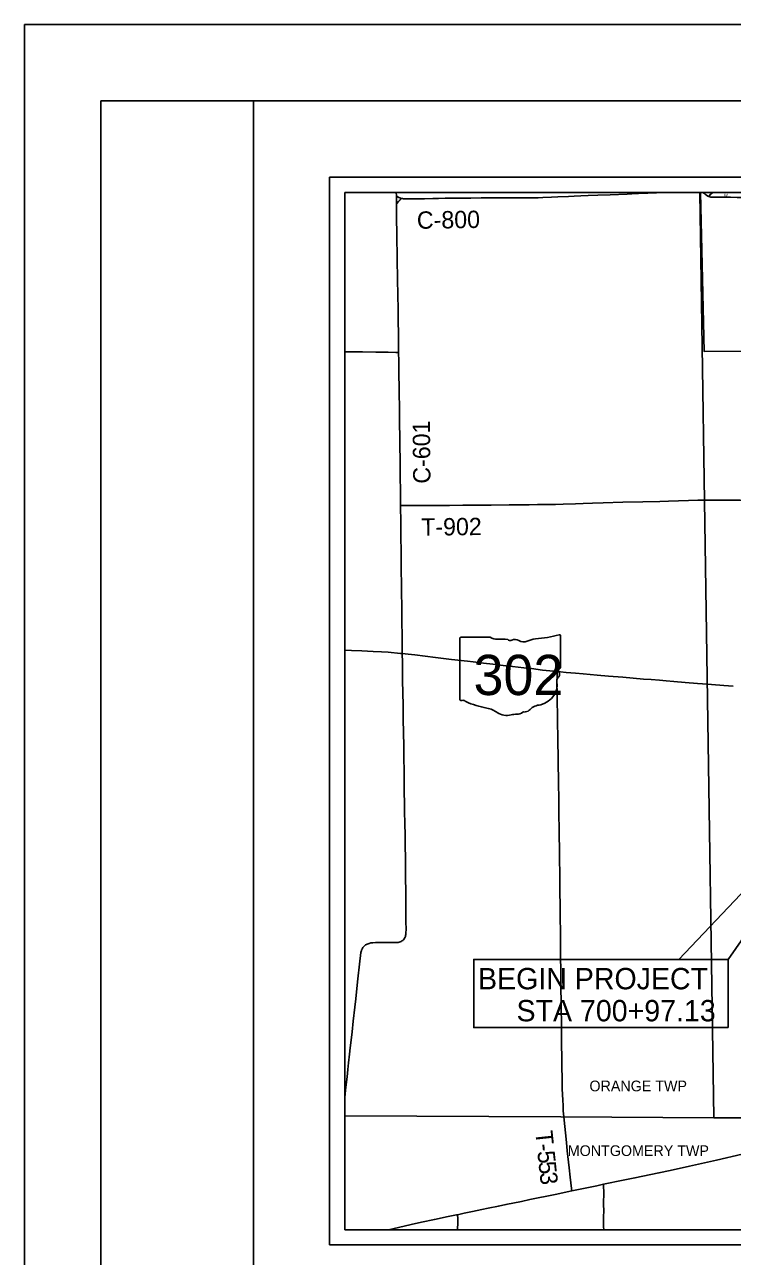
# Model space of a CAD drawing. Extents: x 0 to 72, y -85 to 22.
# Drawn here: x 0 to 4.64, y 13.93 to 22 of the extents above; entities that cross this region are included whole.
import ezdxf

# ---------------------------------------------------------------- set-up
doc = ezdxf.new("R2010")
doc.units = 0
for name, color, linetype in [('Default', 7, 'Continuous'), ('GM_X_Adjacent_County', 7, 'Continuous'), ('GM_X_County', 7, 'Continuous'), ('GM_X_County_Road', 7, 'Continuous'), ('GM_X_County_Road_Text', 7, 'Continuous'), ('GM_X_Interstate_Location', 7, 'Continuous'), ('GM_X_Minor_Lake', 7, 'Continuous'), ('GM_X_Minor_River_Text', 7, 'Continuous'), ('GM_X_Section', 7, 'Continuous'), ('GM_X_Section_Text', 7, 'Continuous'), ('GM_X_State_Location', 7, 'Continuous'), ('GM_X_Township', 7, 'Continuous'), ('GM_X_Township_Road', 7, 'Continuous'), ('GM_X_Township_Road_Text', 7, 'Continuous'), ('GM_X_Township_Subdivision', 7, 'Continuous'), ('GM_X_Township_Subdivision_Text', 7, 'Continuous'), ('GM_X_Township_Text', 7, 'Continuous'), ('GM_X_US_Location', 7, 'Continuous')]:
    doc.layers.add(name, color=color, linetype=linetype)

msp = doc.modelspace()

# ---------------------------------------------------------------- linework, layer by layer
at = {"layer": 'Default'}
for p, q in [((8.9, 20.9), (2.1, 20.9)), ((2.1, 20.9), (2.1, 14.1)), ((8.9, 20.9), (2.1, 20.9)), ((2.1, 20.9), (2.1, 14.1)), ((2.1, 14.1), (8.9, 14.1)), ((2.1, 14.1), (8.9, 14.1))]:
    msp.add_line(p, q, dxfattribs=at)
at = {"layer": 'GM_X_Adjacent_County'}
for points in [[(4.6126, 15.8721), (4.2903, 15.8721), (5.5075, 17.154)], [(4.6126, 15.4251), (4.6126, 15.8721), (2.9445, 15.8721), (2.9445, 15.4251)]]:
    msp.add_lwpolyline(points, close=True, dxfattribs=at)
at = {"layer": 'GM_X_County'}
for points in [[(0.5, 21.5), (1.5, 21.5), (1.5, 0.5), (0.5, 0.5)], [(1.5, 21.5), (33.5, 21.5), (33.5, 0.5), (1.5, 0.5)]]:
    msp.add_lwpolyline(points, close=True, dxfattribs=at)
at = {"layer": 'GM_X_County_Road_Text'}
for points in [[(2.1, 19.8551), (2.1598, 19.8546), (2.2158, 19.8547), (2.3028, 19.8538), (2.3836, 19.8517), (2.4333, 19.851), (2.4524, 19.8508)], [(2.4647, 18.8472), (2.4866, 18.8472), (2.555, 18.8471), (2.6048, 18.8475), (2.7167, 18.848), (2.7851, 18.8485), (2.8722, 18.8496), (2.9593, 18.8499), (3.0589, 18.8507), (3.1771, 18.8513), (3.2641, 18.8518), (3.3077, 18.8521), (3.3635, 18.8533), (3.4319, 18.8543), (3.4817, 18.8545), (3.5314, 18.8556), (3.6122, 18.8587), (3.662, 18.8606), (3.7241, 18.8627), (3.7924, 18.8648), (3.923, 18.8687), (4.0536, 18.8719), (4.1655, 18.8747), (4.2214, 18.8762), (4.3519, 18.8801), (4.4141, 18.8819), (4.459, 18.8836)], [(4.459, 18.8836), (4.5056, 18.8836), (4.5801, 18.8824), (4.6484, 18.8819), (4.6918, 18.8815), (4.7414, 18.8808), (4.7787, 18.8804), (4.8595, 18.8799), (4.9092, 18.8798), (4.9403, 18.8794), (5.0333, 18.878), (5.0954, 18.8773), (5.2072, 18.8763), (5.2756, 18.8759), (5.3502, 18.8751), (5.4124, 18.8744), (5.4559, 18.8746), (5.4647, 18.8744)], [(3.535, 14.8391), (3.5317, 14.88), (3.5301, 14.9139), (3.5284, 14.9484), (3.5251, 15.023), (3.5245, 15.1038), (3.523, 15.1536), (3.522, 15.1847), (3.5222, 15.2406), (3.5212, 15.3027), (3.5203, 15.4146), (3.5178, 15.5887), (3.5162, 15.6882), (3.5152, 15.7939), (3.5146, 15.8933), (3.5134, 15.999), (3.5112, 16.198), (3.5099, 16.3411), (3.509, 16.4219), (3.5084, 16.4592), (3.5076, 16.5027), (3.5072, 16.54), (3.5066, 16.5836), (3.5049, 16.6955), (3.5041, 16.7452), (3.5033, 16.8011), (3.5019, 16.8445), (3.5017, 16.8757), (3.5017, 16.9254), (3.4998, 17.0248), (3.4954, 17.3234), (3.494, 17.4291), (3.4911, 17.6095), (3.4906, 17.6903), (3.4909, 17.7339), (3.4914, 17.7464), (3.4918, 17.7591)], [(3.5883, 14.3539), (3.5865, 14.3702), (3.578, 14.4439), (3.5707, 14.5054), (3.5581, 14.6161), (3.5527, 14.6716), (3.535, 14.8391)], [(3.7968, 14.1), (3.7967, 14.1199), (3.7965, 14.1822), (3.7968, 14.2258), (3.7966, 14.2632), (3.7969, 14.3503), (3.796, 14.3814), (3.7956, 14.3975)], [(2.8393, 14.1), (2.8399, 14.1489), (2.8396, 14.1736), (2.839, 14.1983)]]:
    msp.add_lwpolyline(points, dxfattribs=at)
at = {"layer": 'GM_X_Interstate_Location'}
msp.add_lwpolyline([(4.6467, 17.6627), (4.5847, 17.6673), (4.5042, 17.673), (4.4767, 17.6752), (4.4113, 17.6804), (4.3309, 17.6876), (4.2566, 17.694), (4.2071, 17.6983), (4.1637, 17.7021), (4.1079, 17.7063), (4.0584, 17.7101), (3.9903, 17.7156), (3.9222, 17.7215), (3.8293, 17.7294), (3.755, 17.736), (3.6621, 17.744), (3.6126, 17.7481), (3.5507, 17.7534), (3.5136, 17.7568), (3.4918, 17.7591), (3.3963, 17.769), (3.3225, 17.7781), (3.2731, 17.7836), (3.2361, 17.7875), (3.1991, 17.7916), (3.1559, 17.7963), (3.0695, 17.8065), (3.0078, 17.8139), (2.94, 17.8224), (2.903, 17.8267), (2.7981, 17.8387), (2.6934, 17.8518), (2.5576, 17.8676), (2.5144, 17.8728), (2.4754, 17.8768), (2.4649, 17.8779), (2.3844, 17.8851), (2.341, 17.8885), (2.2851, 17.8913), (2.2106, 17.8951), (2.1423, 17.8978), (2.1, 17.8997)], dxfattribs=at)
at = {"layer": 'GM_X_Minor_Lake'}
for points in [[(4.428, 20.9), (4.5196, 14.8337), (3.516, 14.8392), (2.1, 14.8468)], [(8.9, 14.8286), (4.755, 14.8337), (4.5196, 14.8337), (4.428, 20.9)], [(2.1, 14.8468), (3.516, 14.8392), (4.5196, 14.8337), (4.755, 14.8337), (4.7514, 14.1)]]:
    msp.add_lwpolyline(points, dxfattribs=at)
at = {"layer": 'GM_X_Minor_River_Text'}
msp.add_line((2.4375, 20.8768), (2.4371, 20.9), dxfattribs=at)
for points in [[(2.4382, 20.8261), (2.438, 20.8502), (2.4375, 20.8768)], [(2.4375, 20.8768), (2.4482, 20.8698), (2.4534, 20.8664), (2.4592, 20.8636), (2.4653, 20.8615), (2.471, 20.8602)], [(2.4382, 20.8261), (2.4511, 20.8406), (2.4549, 20.8449), (2.4569, 20.8468), (2.4591, 20.8489), (2.4618, 20.8516), (2.4652, 20.8546), (2.471, 20.8602)], [(2.471, 20.8602), (2.4715, 20.8601), (2.4778, 20.8593), (2.484, 20.8589), (2.5277, 20.8583), (2.5962, 20.8583), (2.621, 20.8588), (2.6768, 20.8598), (2.714, 20.8606), (2.7574, 20.8614), (2.8195, 20.8619), (2.8754, 20.8624), (2.9252, 20.8629), (2.9936, 20.8635), (3.0371, 20.8637), (3.1303, 20.8646), (3.1801, 20.8649), (3.2671, 20.8651), (3.3293, 20.8642), (3.3667, 20.8644), (3.3977, 20.8659), (3.4536, 20.8689), (3.4971, 20.871), (3.5654, 20.874), (3.6027, 20.8759), (3.6461, 20.8774), (3.6959, 20.879), (3.758, 20.8813), (3.8387, 20.8846), (3.9505, 20.8894), (3.9815, 20.8907), (4.025, 20.892), (4.0871, 20.8946), (4.1431, 20.897), (4.2055, 20.9)], [(2.4524, 19.8508), (2.4512, 19.9373), (2.4507, 19.9808), (2.4498, 20.0491), (2.4482, 20.1424), (2.4466, 20.2169), (2.4461, 20.2418), (2.4448, 20.3162), (2.4441, 20.3721), (2.4437, 20.4218), (2.4431, 20.4715), (2.4422, 20.5212), (2.4416, 20.5647), (2.441, 20.5958), (2.4402, 20.6455), (2.4394, 20.7136), (2.4391, 20.7508), (2.4387, 20.7819), (2.4382, 20.8254), (2.4382, 20.8261)], [(2.4588, 19.371), (2.4586, 19.3842), (2.458, 19.4215), (2.4574, 19.4712), (2.4562, 19.6017), (2.4545, 19.726), (2.4534, 19.7943), (2.4524, 19.8508)], [(2.4647, 18.8472), (2.4647, 18.8498), (2.4639, 18.9244), (2.4623, 19.0549), (2.4613, 19.1606), (2.4607, 19.2227), (2.4599, 19.2724), (2.4594, 19.3159), (2.4589, 19.3656), (2.4588, 19.371)], [(2.4754, 17.8768), (2.475, 17.8927), (2.4745, 17.9859), (2.4739, 18.0916), (2.4732, 18.16), (2.473, 18.1973), (2.4719, 18.2656), (2.4708, 18.3402), (2.4698, 18.4147), (2.4681, 18.5577), (2.4676, 18.6323), (2.4665, 18.7193), (2.4661, 18.769), (2.4654, 18.8125), (2.4647, 18.8472)], [(2.1, 14.9656), (2.105, 15.0153), (2.109, 15.0523), (2.1143, 15.1016), (2.1197, 15.151), (2.1243, 15.1943), (2.1302, 15.2499), (2.1348, 15.2931), (2.1404, 15.3424), (2.1469, 15.398), (2.1544, 15.4659), (2.1644, 15.5586), (2.1706, 15.6142), (2.1823, 15.7255), (2.1973, 15.8614), (2.2018, 15.8984), (2.2048, 15.9166), (2.2061, 15.9226), (2.2078, 15.9285), (2.2098, 15.9342), (2.2123, 15.9397), (2.2151, 15.945), (2.2185, 15.95), (2.2222, 15.9547), (2.2264, 15.9591), (2.231, 15.9629), (2.236, 15.9665), (2.2412, 15.9695), (2.2466, 15.9722), (2.2581, 15.9765), (2.2699, 15.9795), (2.2821, 15.9814), (2.3005, 15.9828), (2.3315, 15.9831), (2.3937, 15.9819), (2.4311, 15.9817), (2.4437, 15.9827), (2.4499, 15.9837), (2.4561, 15.9852), (2.4622, 15.9872), (2.468, 15.9898), (2.4736, 15.993), (2.4788, 15.9967), (2.4835, 16.0011), (2.4876, 16.006), (2.4912, 16.0113), (2.4942, 16.017), (2.4965, 16.023), (2.4981, 16.0292), (2.4991, 16.0355), (2.5002, 16.048), (2.5007, 16.0668), (2.4999, 16.1227), (2.4999, 16.1662), (2.4993, 16.2282), (2.499, 16.2654), (2.4988, 16.2964), (2.4986, 16.3337), (2.4984, 16.3896), (2.4976, 16.4764), (2.4967, 16.551), (2.496, 16.6007), (2.4955, 16.638), (2.4942, 16.7063), (2.4934, 16.7436), (2.4926, 16.7808), (2.4917, 16.8243), (2.4904, 16.8862), (2.49, 16.9234), (2.4894, 16.942), (2.4887, 16.9793), (2.4876, 17.0849), (2.4864, 17.2154), (2.4856, 17.2838), (2.4845, 17.3459), (2.4822, 17.4578), (2.4812, 17.5385), (2.4799, 17.6193), (2.4786, 17.7001), (2.4769, 17.7809), (2.4768, 17.8181), (2.4754, 17.8768)]]:
    msp.add_lwpolyline(points, dxfattribs=at)
at = {"layer": 'GM_X_Section'}
msp.add_lwpolyline([(0, 0), (34, 0), (34, 22), (0, 22)], close=True, dxfattribs=at)
at = {"layer": 'GM_X_Section_Text'}
for points in [[(4.4478, 20.9), (4.4505, 20.8981), (4.4598, 20.8899), (4.4647, 20.8859), (4.4699, 20.8823), (4.4808, 20.876), (4.4859, 20.8737)], [(4.4859, 20.8737), (4.492, 20.8814), (4.4977, 20.8877), (4.5021, 20.8917), (4.5134, 20.9)], [(4.4859, 20.8737), (4.4866, 20.8734), (4.4926, 20.8712), (4.4987, 20.8696), (4.5051, 20.8687), (4.5113, 20.8683), (4.5548, 20.8679), (4.6292, 20.8681), (4.6726, 20.8678), (4.7284, 20.8676), (4.7903, 20.8675), (4.8709, 20.8676), (4.9515, 20.8666), (5.0258, 20.8658), (5.1498, 20.865), (5.218, 20.865), (5.2924, 20.8644), (5.3978, 20.8644), (5.4598, 20.863)]]:
    msp.add_lwpolyline(points, dxfattribs=at)
at = {"layer": 'GM_X_State_Location'}
msp.add_lwpolyline([(2.3864, 14.1), (2.4506, 14.1147), (2.5354, 14.1344), (2.602, 14.1492), (2.6869, 14.1673), (2.778, 14.1862), (2.8328, 14.1973), (2.839, 14.1983), (2.8815, 14.2073), (2.9363, 14.2188), (2.9972, 14.2313), (3.0397, 14.2404), (3.1066, 14.2542), (3.1553, 14.2641), (3.2587, 14.2857), (3.3135, 14.297), (3.4779, 14.3308), (3.5874, 14.3537), (3.5883, 14.3539), (3.7516, 14.3882), (3.7956, 14.3975), (3.8184, 14.4024), (3.9037, 14.42), (4.0012, 14.4395), (4.1595, 14.4719), (4.2324, 14.4877), (4.3597, 14.5164), (4.5355, 14.5559), (4.7053, 14.5943)], dxfattribs=at)
at = {"layer": 'GM_X_Township'}
for p, q in [((2, 21), (9, 21)), ((2, 21), (2, 14)), ((2, 14), (9, 14))]:
    msp.add_line(p, q, dxfattribs=at)
at = {"layer": 'GM_X_Township_Subdivision_Text'}
msp.add_lwpolyline([(6.4631, 20.9), (6.4627, 19.8722), (4.4549, 19.8575), (4.4327, 20.9)], dxfattribs=at)
at = {"layer": 'GM_X_US_Location'}
for p, q in [((2.8539, 17.9769), (2.8539, 17.5766)), ((3.0534, 17.9838), (2.8604, 17.9838)), ((3.5131, 17.7843), (3.5131, 17.9937)), ((3.513, 17.7844), (3.5131, 17.7843))]:
    msp.add_line(p, q, dxfattribs=at)
for centre, major_axis, start_param, end_param in [((2.8614, 17.9777), (0.00764, 0), 1.712693, 3.28349), ((3.0994, 18.0302), (0.0741, 0), 4.042523, 4.731795), ((3.124, 17.7591), (0.2659, 0), 1.404758, 1.657858), ((3.1843, 17.9798), (0.0214, 0), 3.836095, 5.185415), ((3.2157, 17.9336), (0.0444, 0), 0.950623, 2.079405), ((3.273, 17.997), (0.0534, 0), 4.081561, 5.145723), ((3.3674, 17.8615), (0.1406, 0), 1.699011, 2.107814), ((3.2783, 18.5294), (0.699, 0), 4.814394, 5.042369), ((3.5058, 17.9946), (0.00734, 0), 6.141152, 7.989035), ((3.5114, 17.769), (0.0114, 0), 1.883978, 3.671073), ((3.5052, 17.7835), (0.00785, 0), 5.05454, 6.418171), ((3.3174, 17.6701), (0.1748, 0), 5.101752, 6.440018), ((3.5394, 17.6967), (0.0496, 0), 2.387724, 3.262537), ((3.4391, 17.7425), (0.0682, 0), 5.934695, 6.695948), ((2.8615, 17.5758), (0.0077, 0), 3.00124, 4.508301), ((2.8627, 17.6167), (0.0588, 0), 4.665946, 4.897461), ((2.8747, 17.5536), (0.0212, 0), 0.519207, 1.627899), ((3.1424, 17.9132), (0.5048, 0), 4.195997, 4.488961), ((3.3911, 17.4643), (0.0958, 0), 1.647645, 2.488434), ((2.9919, 17.3968), (0.1579, 0), 0.823519, 1.323587), ((3.1627, 17.5516), (0.1002, 0), 4.026481, 4.996735), ((3.2206, 17.4132), (0.0824, 0), 1.495662, 1.94098), ((3.2279, 17.5216), (0.0534, 0), 4.691044, 5.507374), ((3.2762, 17.4828), (0.015, 0), 1.147584, 2.315152), ((3.2698, 17.5379), (0.0565, 0), 4.937069, 5.64225)]:
    msp.add_ellipse(centre, major_axis=major_axis, ratio=0.8, start_param=start_param, end_param=end_param, dxfattribs=at)

# ---------------------------------------------------------------- texts
at = {"layer": 'GM_X_Adjacent_County'}
for s, height, p in [('BEGIN PROJECT', 0.14, (2.9728, 15.6758)), ('STA 700+97.13', 0.14, (3.2253, 15.4658)), ('ORANGE TWP', 0.07, (3.7035, 15.0072)), ('MONTGOMERY TWP', 0.07, (3.5615, 14.583))]:
    msp.add_text(s, height=height, dxfattribs=at).set_placement(p)
at = {"layer": 'GM_X_County_Road'}
for s, rotation, p in [('C-800', 0.82606, (2.5728, 20.6613)), ('C-601', 90.55164, (2.6614, 18.991))]:
    msp.add_text(s, height=0.11364, rotation=rotation, dxfattribs=at).set_placement(p)
at = {"layer": 'GM_X_Township_Road'}
for s, height, rotation, p in [('T-902', 0.11364, 0.55923, (2.6008, 18.6498)), ('T', 0.1136, 275.98524, (3.3476, 14.7438)), ('-', 0.1136, 275.98246, (3.3565, 14.6592)), ('5', 0.1136, 276.01768, (3.3614, 14.6127)), ('5', 0.1136, 276.0991, (3.3687, 14.543)), ('3', 0.1136, 276.48, (3.3763, 14.4725))]:
    msp.add_text(s, height=height, rotation=rotation, dxfattribs=at).set_placement(p)
at = {"layer": 'GM_X_Township_Road_Text'}
msp.add_text('302', height=0.000379, rotation=0.00001, dxfattribs=at).set_placement((3.0424, 17.7226))
for s in ['s', 'r']:
    msp.add_text(s, height=0.000379, dxfattribs=at).set_placement((3.1761, 17.7502))
at = {"layer": 'GM_X_Township_Subdivision'}
for s in ['0', '/']:
    msp.add_text(s, height=0.000379, dxfattribs=at).set_placement((2.4489, 14.116))
at = {"layer": 'GM_X_Township_Text'}
msp.add_text('W', height=0.0189, rotation=0.00001, dxfattribs=at).set_placement((4.5857, 20.8723))
at = {"layer": 'GM_X_US_Location'}
msp.add_text('302', height=0.26367, dxfattribs=at).set_placement((2.9434, 17.6049))

doc.saveas('drawing.dxf')
